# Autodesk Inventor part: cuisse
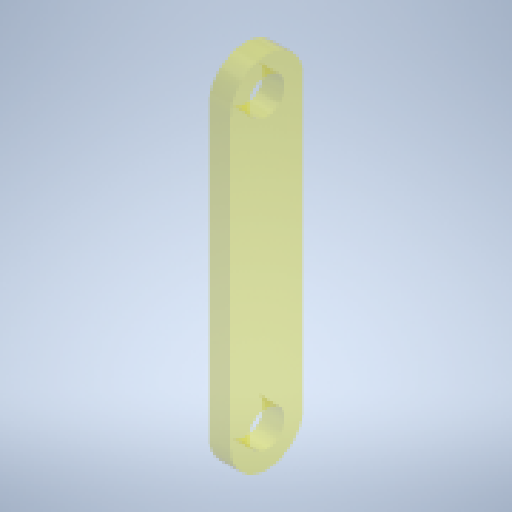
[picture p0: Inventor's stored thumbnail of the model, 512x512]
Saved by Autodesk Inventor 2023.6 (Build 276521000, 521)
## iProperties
Created: 2026-01
Part Number: cuisse
Material: Générique
Document SubType Name: Modeling
Designer: mel
Density: 1 g/cm^3
Appearance: Terre battue - Brun foncé
Author: mel
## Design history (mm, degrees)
sketch "Esquisse2"
  geometry: L1 (0, 5)-(-40, 5); L2 (0, -5)-(-40, -5); C1 r 2.5 at (0, 0); C2 r 2.5 at (-40, 0); A1 r 5 centre (0, 0) between (0, -5) and (0, 5); A2 r 5 centre (-40, 0) between (-40, 5) and (-40, -5); 1 further point
  constraints: 4 centre point, 4 end point, 4 point on circle, 4 tangent, 3 coincident
  dimensions: "d0" = 10 diameter of A1; "d1" = 10 diameter of A2; "d2" = 5 diameter of C1; "d3" = 5 diameter of C2; "d6" = 40 distance of A2.centre point (0, 0)
extrude "Extrusion1" new body sketch "Esquisse2" distance "d4" = 3; taper "d5" = 0 deg
node "Solide1"
